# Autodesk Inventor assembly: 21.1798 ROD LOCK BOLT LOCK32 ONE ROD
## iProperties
Created: 2007-03
Part Number: 21.1798 ROD LOCK BOLT LOCK32 ONE ROD
Document SubType Name: Assembly
Designer: Andy Moles
Author: Andy Moles
